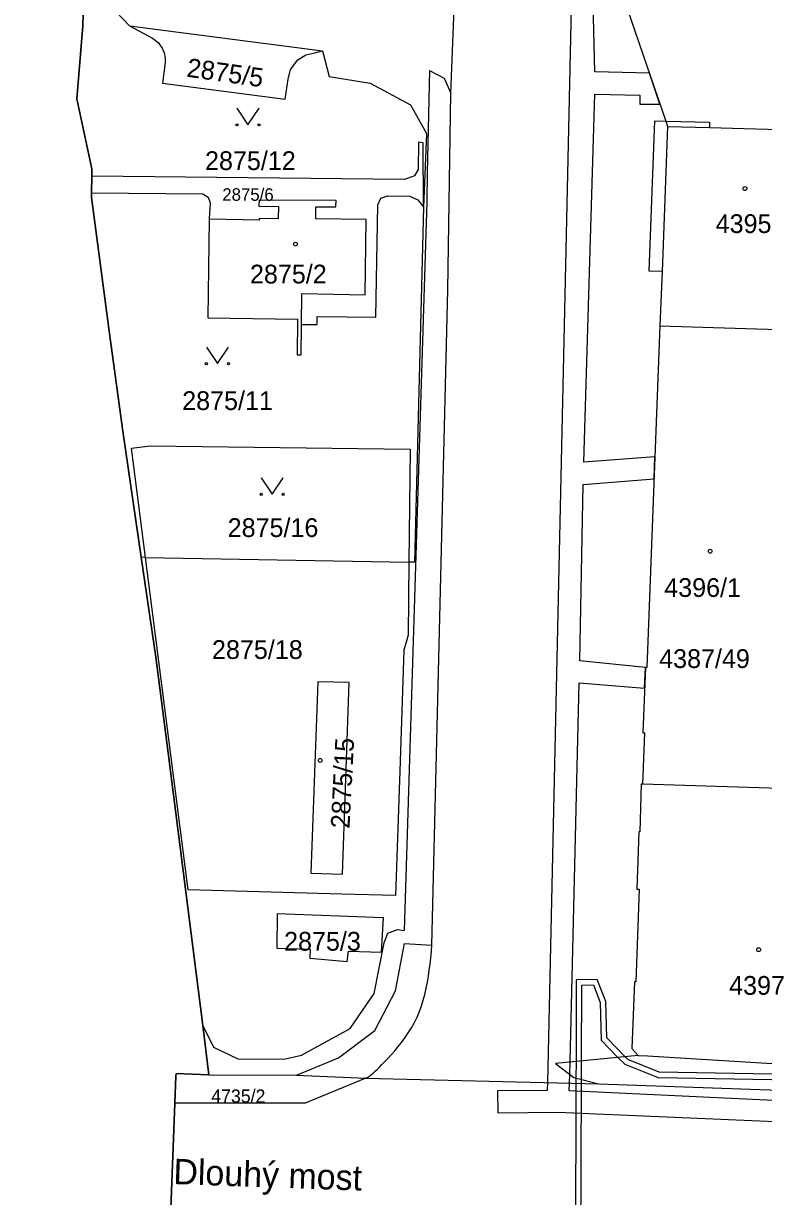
# Model space of a CAD drawing. Extents: x -756746 to -753363, y -1166406 to -1161727.
# Drawn here: x -756329.6 to -756262.6, y -1165730.9 to -1165624.6 of the extents above; entities that cross this region are included whole.
import ezdxf

# ---------------------------------------------------------------- set-up
doc = ezdxf.new("R2010")
doc.units = 0
for name, color, linetype in [('Hranice kat_území', 7, 'Continuous'), ('Hranice parcel', 7, 'Continuous'), ('Parcelní čísla', 7, 'Continuous'), ('Pop  PČ popisy', 7, 'Continuous'), ('Vnitřní kresba', 7, 'Continuous'), ('Věcná břemena k části', 7, 'Continuous'), ('Značky budov', 7, 'Continuous'), ('Značky kultur', 7, 'Continuous')]:
    doc.layers.add(name, color=color, linetype=linetype)

msp = doc.modelspace()

# ---------------------------------------------------------------- linework, layer by layer
at = {"layer": 'Hranice kat_území'}
msp.add_lwpolyline([(-756324.11, -1165620.45), (-756324.24, -1165624.79), (-756324.8, -1165631.39), (-756323.42, -1165637.73), (-756323.43, -1165638.41), (-756323.45, -1165639.91), (-756323.45, -1165640.33), (-756321.77, -1165653.11), (-756320.63, -1165661.53), (-756318.96, -1165672.95), (-756317.63, -1165681.99), (-756316.52, -1165690.68), (-756313.37, -1165715.37), (-756312.84, -1165719.86), (-756315.8, -1165719.73), (-756315.81, -1165719.97), (-756315.9, -1165722.43), (-756316.27, -1165731.97)], dxfattribs=at)
at = {"layer": 'Hranice parcel'}
for p, q in [((-756324.11, -1165620.45), (-756320, -1165624.79)), ((-756320, -1165624.79), (-756302.52, -1165627.05)), ((-756323.45, -1165639.91), (-756323.43, -1165638.41)), ((-756318.57, -1165672.96), (-756318.96, -1165672.95)), ((-756318.57, -1165672.96), (-756294.7, -1165673.38)), ((-756312.84, -1165719.86), (-756304.9, -1165719.87)), ((-756304.9, -1165719.87), (-756298.6, -1165720.16)), ((-756298.6, -1165720.16), (-756304.11, -1165722.41)), ((-756298.6, -1165720.16), (-756277.51, -1165720.66)), ((-756316.27, -1165731.97), (-756315.9, -1165722.43)), ((-756304.11, -1165722.41), (-756315.9, -1165722.43))]:
    msp.add_line(p, q, dxfattribs=at)
for points in [[(-756292.62, -1165708.1), (-756291.19, -1165648.7), (-756290.89, -1165630.89), (-756290.24, -1165614.03), (-756291.21, -1165610.06), (-756302.74, -1165574.26), (-756310.88, -1165548.49), (-756323.64, -1165508), (-756337.93, -1165468.42), (-756358.43, -1165418.45), (-756368.85, -1165398.15), (-756409.24, -1165342.83), (-756436.19, -1165309.61), (-756456.31, -1165288.98), (-756449.84, -1165283.06)], [(-756323.43, -1165638.41), (-756323.42, -1165637.73), (-756324.8, -1165631.39), (-756324.24, -1165624.79), (-756324.11, -1165620.45)], [(-756275.96, -1165620.18), (-756271.44, -1165633.41), (-756271.27, -1165633.89)], [(-756320, -1165624.79), (-756317.93, -1165625.9), (-756317.43, -1165626.29), (-756317.05, -1165626.8), (-756316.87, -1165627.24), (-756316.78, -1165627.71), (-756316.78, -1165628.11), (-756317.04, -1165629.97), (-756305.9, -1165631.43), (-756305.65, -1165629.6), (-756305.42, -1165628.75), (-756304.77, -1165627.87), (-756304.04, -1165627.42), (-756303.21, -1165627.22), (-756302.52, -1165627.05)], [(-756302.52, -1165627.05), (-756301.94, -1165629.38), (-756298.22, -1165629.97), (-756294.56, -1165631.94), (-756293.12, -1165634.53), (-756293.39, -1165641.2)], [(-756271.27, -1165633.89), (-756271.77, -1165647.06), (-756271.96, -1165651.98)], [(-756271.27, -1165633.89), (-756267.48, -1165634), (-756255.95, -1165634.33)], [(-756293.39, -1165641.2), (-756293.41, -1165635.39), (-756293.82, -1165635.33), (-756293.87, -1165637.81), (-756294.19, -1165638.38), (-756295.11, -1165638.72), (-756323.43, -1165638.41)], [(-756323.45, -1165639.91), (-756313.38, -1165640.01), (-756312.89, -1165640.31), (-756312.72, -1165640.83), (-756312.79, -1165642.31)], [(-756318.96, -1165672.95), (-756320.63, -1165661.53), (-756321.77, -1165653.11), (-756323.45, -1165640.33), (-756323.45, -1165639.91)], [(-756304.43, -1165651.86), (-756304.4, -1165649.03), (-756298.67, -1165649.17), (-756298.56, -1165642.32), (-756303.14, -1165642.28), (-756303.13, -1165641.17), (-756301.32, -1165641.19), (-756301.3, -1165640.61), (-756308.28, -1165640.58), (-756308.29, -1165641.13), (-756306.53, -1165641.16), (-756306.55, -1165642.27), (-756308.28, -1165642.24), (-756308.28, -1165642.38), (-756312.79, -1165642.31)], [(-756304.43, -1165651.86), (-756303, -1165651.85), (-756303.01, -1165651.12), (-756297.7, -1165651.18), (-756297.51, -1165641.01), (-756297.24, -1165640.41), (-756296.62, -1165640.2), (-756294.63, -1165640.22), (-756293.89, -1165640.55), (-756293.39, -1165641.2)], [(-756293.39, -1165641.2), (-756294.21, -1165673.39), (-756294.7, -1165673.38)], [(-756312.79, -1165642.31), (-756312.93, -1165651.24), (-756304.78, -1165651.37), (-756304.83, -1165654.6), (-756304.46, -1165654.6), (-756304.43, -1165651.86)], [(-756271.96, -1165651.98), (-756273.14, -1165682.95), (-756273.28, -1165682.94), (-756273.5, -1165688.87), (-756273.37, -1165688.87), (-756273.55, -1165693.51)], [(-756271.96, -1165651.98), (-756261.24, -1165652.29), (-756260.51, -1165652.26), (-756256.72, -1165652.36)], [(-756318.57, -1165672.96), (-756319.84, -1165663.07), (-756318.13, -1165662.84), (-756294.6, -1165663.16), (-756294.7, -1165673.38)], [(-756312.84, -1165719.86), (-756313.37, -1165715.37), (-756316.52, -1165690.68), (-756317.63, -1165681.99), (-756318.96, -1165672.95)], [(-756294.7, -1165673.38), (-756294.76, -1165680.01), (-756295.15, -1165681.38), (-756295.49, -1165691.43), (-756295.92, -1165703.61), (-756300.79, -1165703.47), (-756314.7, -1165703.09), (-756318.57, -1165672.96)], [(-756300.72, -1165701.68), (-756300.35, -1165691.28), (-756300.1, -1165684.31), (-756302.95, -1165684.24), (-756303.58, -1165701.59), (-756300.72, -1165701.68)], [(-756273.55, -1165693.51), (-756273.65, -1165693.51), (-756273.77, -1165697.83), (-756273.87, -1165697.82), (-756274.05, -1165703.02), (-756273.85, -1165703.03), (-756274.15, -1165711.44), (-756274.26, -1165711.43), (-756274.52, -1165717.48), (-756273.93, -1165718.09)], [(-756255.85, -1165694.05), (-756259.86, -1165693.93), (-756260.09, -1165693.93), (-756261.09, -1165693.9), (-756273.55, -1165693.51)], [(-756306.63, -1165705.27), (-756306.67, -1165708.36), (-756303.66, -1165708.45), (-756303.69, -1165709.29), (-756300.29, -1165709.57), (-756300.17, -1165708.64), (-756297.19, -1165708.73), (-756297.01, -1165705.61), (-756306.63, -1165705.27)], [(-756304.9, -1165719.87), (-756301.08, -1165718.32), (-756297.79, -1165715.83), (-756295.92, -1165712.23), (-756295.11, -1165707.95), (-756292.62, -1165708.1)], [(-756273.93, -1165718.09), (-756281.43, -1165718.82), (-756279.75, -1165720.11), (-756277.51, -1165720.66)], [(-756273.93, -1165718.09), (-756273.08, -1165718.12), (-756261.78, -1165718.83), (-756258.72, -1165718.92), (-756258.72, -1165718.82), (-756249.71, -1165719.15)], [(-756315.9, -1165722.43), (-756315.81, -1165719.97), (-756315.8, -1165719.73), (-756312.84, -1165719.86)], [(-756277.51, -1165720.66), (-756158.23, -1165724.87), (-756155.42, -1165723.51), (-756154.72, -1165722.41)]]:
    msp.add_lwpolyline(points, dxfattribs=at)
at = {"layer": 'Vnitřní kresba'}
for p, q in [((-756292.85, -1165628.84), (-756293.05, -1165638.1)), ((-756292.85, -1165628.84), (-756291.51, -1165629.52)), ((-756291.51, -1165629.52), (-756290.89, -1165630.89)), ((-756272.93, -1165647.02), (-756272.41, -1165633.38)), ((-756272.41, -1165633.38), (-756271.44, -1165633.41)), ((-756271.44, -1165633.41), (-756267.46, -1165633.52)), ((-756267.46, -1165633.52), (-756267.48, -1165634)), ((-756293.05, -1165638.1), (-756293.08, -1165640.69)), ((-756293.08, -1165640.69), (-756295.12, -1165706.77)), ((-756271.77, -1165647.06), (-756272.93, -1165647.02)), ((-756296.62, -1165707.02), (-756295.74, -1165706.67)), ((-756295.74, -1165706.67), (-756295.12, -1165706.77)), ((-756297.86, -1165712.48), (-756296.93, -1165707.88)), ((-756296.93, -1165707.88), (-756296.62, -1165707.02)), ((-756300.01, -1165715.65), (-756297.86, -1165712.48)), ((-756313.37, -1165715.37), (-756312.4, -1165717.36)), ((-756304.43, -1165718.07), (-756300.01, -1165715.65)), ((-756312.4, -1165717.36), (-756310.21, -1165718.4)), ((-756310.21, -1165718.4), (-756306.02, -1165718.44)), ((-756306.02, -1165718.44), (-756304.43, -1165718.07))]:
    msp.add_line(p, q, dxfattribs=at)
msp.add_lwpolyline([(-756298.6, -1165720.16), (-756298.56, -1165720.14), (-756298.51, -1165720.12), (-756298.46, -1165720.1), (-756298.41, -1165720.07), (-756298.34, -1165720.02), (-756298.26, -1165719.96), (-756298.17, -1165719.89), (-756298.06, -1165719.79), (-756297.92, -1165719.68), (-756297.77, -1165719.53), (-756297.59, -1165719.36), (-756297.38, -1165719.16), (-756297.14, -1165718.93), (-756296.88, -1165718.66), (-756296.6, -1165718.36), (-756296.3, -1165718.03), (-756295.99, -1165717.68), (-756295.68, -1165717.3), (-756295.37, -1165716.91), (-756295.05, -1165716.48), (-756294.76, -1165716.04), (-756294.47, -1165715.58), (-756294.2, -1165715.11), (-756293.96, -1165714.62), (-756293.75, -1165714.12), (-756293.56, -1165713.61), (-756293.4, -1165713.09), (-756293.25, -1165712.56), (-756293.13, -1165712.01), (-756293.03, -1165711.47), (-756292.94, -1165710.92), (-756292.86, -1165710.36), (-756292.79, -1165709.8), (-756292.73, -1165709.24), (-756292.67, -1165708.67), (-756292.62, -1165708.1)], dxfattribs=at)
at = {"layer": 'Věcná břemena k části'}
for points in [[(-756261.01, -1165722.2), (-756280.17, -1165721.3), (-756280.15, -1165720.6), (-756280.13, -1165719.82), (-756280.1, -1165718.69), (-756279.28, -1165684.34), (-756273.35, -1165684.81), (-756273.28, -1165682.94), (-756279.23, -1165682.34), (-756278.91, -1165666.34), (-756272.49, -1165665.84), (-756272.41, -1165663.83), (-756278.86, -1165664.33), (-756277.87, -1165630.96), (-756273.77, -1165631.06), (-756273.79, -1165631.87), (-756271.97, -1165631.87), (-756272.92, -1165629.08), (-756277.86, -1165628.96), (-756278.01, -1165622.75)], [(-756280.01, -1165623.11), (-756282.15, -1165720.55), (-756282.17, -1165721.26), (-756286.67, -1165721.29), (-756286.65, -1165723.29), (-756281.21, -1165723.25), (-756255.9, -1165724.32)], [(-756260.1, -1165719.81), (-756272.03, -1165719.6), (-756274.87, -1165718.47), (-756275.12, -1165718.21), (-756276.78, -1165716.51), (-756276.87, -1165713.2), (-756277.64, -1165711.21), (-756279.54, -1165711.24), (-756279.56, -1165718.64), (-756279.57, -1165720.15), (-756279.57, -1165720.61), (-756279.62, -1165735.22)], [(-756279.12, -1165735.23), (-756279.07, -1165720.62), (-756279.07, -1165720.28), (-756279.06, -1165718.59), (-756279.04, -1165711.74), (-756277.98, -1165711.71), (-756277.37, -1165713.3), (-756277.28, -1165716.71), (-756275.76, -1165718.27), (-756275.15, -1165718.89), (-756272.13, -1165720.1), (-756260.12, -1165720.31)]]:
    msp.add_lwpolyline(points, dxfattribs=at)
at = {"layer": 'Značky budov'}
for centre in [(-756264.26, -1165639.53), (-756304.98, -1165644.57), (-756267.41, -1165672.4), (-756302.74, -1165691.36), (-756263.02, -1165708.51)]:
    msp.add_circle(centre, 0.175, dxfattribs=at)
at = {"layer": 'Značky kultur'}
for points in [[(-756310.28, -1165632.25), (-756309.28, -1165633.75), (-756308.28, -1165632.25)], [(-756313.05, -1165653.89), (-756312.05, -1165655.39), (-756311.05, -1165653.89)], [(-756308.09, -1165665.74), (-756307.09, -1165667.24), (-756306.09, -1165665.74)]]:
    msp.add_lwpolyline(points, dxfattribs=at)
for centre in [(-756310.28, -1165633.75), (-756308.28, -1165633.75), (-756313.05, -1165655.39), (-756311.05, -1165655.39), (-756308.09, -1165667.24), (-756306.09, -1165667.24)]:
    msp.add_circle(centre, 0.1, dxfattribs=at)

# ---------------------------------------------------------------- texts
at = {"layer": 'Parcelní čísla'}
for s, rotation, p in [('2875/5', 352, (-756314.9, -1165629.38)), ('2875/15', 87, (-756300.09, -1165697.56))]:
    msp.add_text(s, height=1.7, rotation=rotation, dxfattribs=at).set_placement(p)
for s, height, p in [('2875/12', 1.7, (-756313.17, -1165637.85)), ('2875/6', 1.139, (-756311.61, -1165640.64)), ('4395', 1.7, (-756266.91, -1165643.56)), ('2875/2', 1.7, (-756309.1, -1165648.13)), ('2875/11', 1.7, (-756315.24, -1165659.6)), ('2875/16', 1.7, (-756311.12, -1165671.11)), ('4396/1', 1.7, (-756271.57, -1165676.54)), ('2875/18', 1.7, (-756312.54, -1165682.16)), ('4387/49', 1.7, (-756272.03, -1165682.98)), ('2875/3', 1.7, (-756306.01, -1165708.6)), ('4397', 1.7, (-756265.69, -1165712.6)), ('4735/2', 1.2, (-756312.61, -1165722.38))]:
    msp.add_text(s, height=height, dxfattribs=at).set_placement(p)
at = {"layer": 'Pop  PČ popisy'}
msp.add_text('Dlouhý most', height=2.3, rotation=358, dxfattribs=at).set_placement((-756316.07, -1165729.75))

doc.saveas('drawing.dxf')
